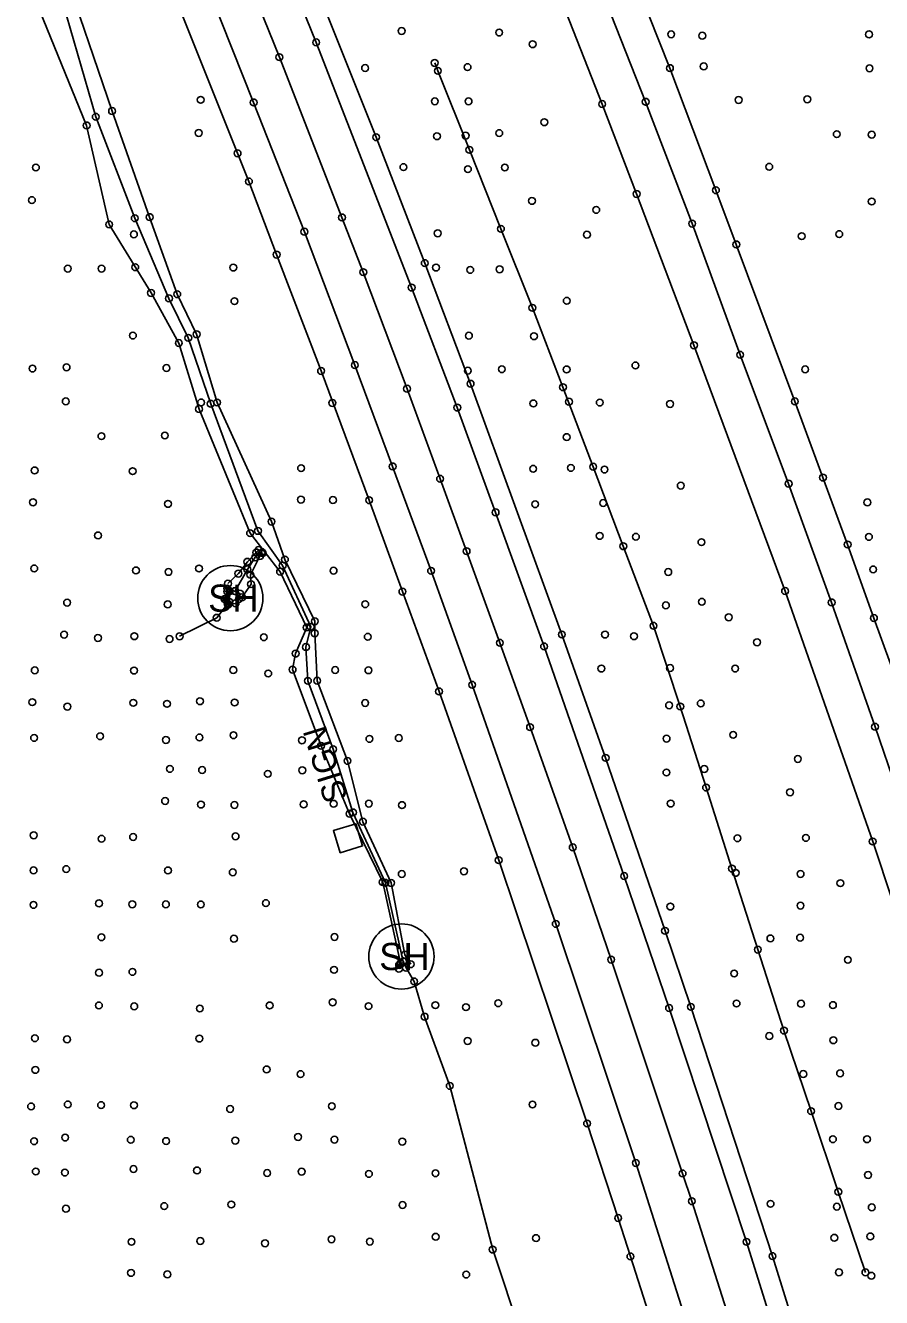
# Model space of a CAD drawing. Extents: x 20503438 to 20508873, y 7964251 to 7984667.
# Drawn here: x 20506193.5 to 20506445, y 7975096.9 to 7975470.8 of the extents above; entities that cross this region are included whole.
import ezdxf

# ---------------------------------------------------------------- set-up
doc = ezdxf.new("R2010")
doc.units = 0
for name, color, linetype in [('SurBreakLine', 7, 'Continuous'), ('SurDrainageArrowDown', 7, 'Continuous'), ('SurDrainageArrowUp', 7, 'Continuous'), ('SurEdgeRoadPaved', 7, 'Continuous'), ('SurEdgeShoulderPaved', 7, 'Continuous'), ('SurNaturalCells', 7, 'Continuous'), ('SurRoadPoints', 7, 'Continuous'), ('SurSurveyPoints', 7, 'Continuous')]:
    doc.layers.add(name, color=color, linetype=linetype)

msp = doc.modelspace()

# ---------------------------------------------------------------- linework, layer by layer
at = {"layer": 'SurBreakLine'}
for points in [[(20506254.12, 7975496.18), (20506268.1, 7975461.5), (20506286.48, 7975414.39), (20506292.75, 7975398.31), (20506305.6, 7975364.06), (20506315.32, 7975337.59), (20506323.1, 7975316.32), (20506332.87, 7975289.39), (20506341.75, 7975264.58), (20506354.3, 7975229.25), (20506365.58, 7975196.27), (20506386.55, 7975133.43), (20506389.28, 7975125.26), (20506400.17, 7975091.1)], [(20506204.02, 7975489.57), (20506218.94, 7975445.66), (20506229.98, 7975414.5), (20506238.08, 7975391.82), (20506243.78, 7975380.06), (20506249.79, 7975360.01), (20506265.78, 7975325), (20506269.72, 7975313.85), (20506278.51, 7975295.7), (20506278.47, 7975292.17), (20506279.19, 7975278.24), (20506288.11, 7975254.67), (20506292.64, 7975236.81), (20506300.9, 7975218.8), (20506304.96, 7975197.71), (20506306.69, 7975194.92)], [(20506193.49, 7975485.46), (20506211.46, 7975441.43), (20506218.08, 7975412.34), (20506230.39, 7975392.2), (20506238.56, 7975377.49), (20506244.49, 7975358.08), (20506259.5, 7975321.6), (20506268.3, 7975310.27), (20506276.12, 7975293.9), (20506272.86, 7975286.21), (20506271.97, 7975281.49), (20506280.33, 7975259.1), (20506288.72, 7975239.15), (20506298.46, 7975219.05), (20506303.7, 7975195.21), (20506303.27, 7975194.67)], [(20506349.14, 7975482.98), (20506362.94, 7975447.73), (20506373.06, 7975421.29), (20506389.9, 7975376.81), (20506416.68, 7975304.59), (20506442.42, 7975230.98), (20506465.81, 7975160.63), (20506487.25, 7975093.26), (20506498.75, 7975056.68), (20506509.78, 7975020.48), (20506520.41, 7974984.15), (20506530.78, 7974947.69), (20506540.38, 7974913.1), (20506559, 7974844.57), (20506576.27, 7974776.6), (20506593.8, 7974705.89)], [(20506261.97, 7975316.64), (20506261.31, 7975315.93), (20506258.68, 7975313.19), (20506256.04, 7975309.71), (20506252.98, 7975306.78)], [(20506256.18, 7975302.21), (20506257.1, 7975302.73), (20506259.76, 7975306.61), (20506259.58, 7975309.35), (20506262.39, 7975314.88), (20506263.18, 7975315.75)]]:
    msp.add_lwpolyline(points, dxfattribs=at)
for points in [[(20506252.82, 7975304.45), (20506252.04, 7975302.25), (20506253.13, 7975300.69), (20506255.22, 7975300.98), (20506256.18, 7975302.21), (20506256.51, 7975303.84), (20506254.95, 7975304.57), (20506252.76, 7975305.32)], [(20506252.5, 7975302.42), (20506253.42, 7975301.39), (20506253.53, 7975304.58)]]:
    msp.add_lwpolyline(points, close=True, dxfattribs=at)
at = {"layer": 'SurDrainageArrowDown'}
msp.add_lwpolyline([(20506440.28, 7975104.35), (20506432.3, 7975128.04), (20506424.32, 7975151.73), (20506416.34, 7975175.42), (20506408.66, 7975199.21), (20506401.07, 7975223.03), (20506393.47, 7975246.84), (20506385.88, 7975270.66), (20506378.02, 7975294.38), (20506369.15, 7975317.76), (20506360.29, 7975341.13), (20506351.42, 7975364.5), (20506342.43, 7975387.83), (20506333.17, 7975411.05), (20506323.91, 7975434.26), (20506314.65, 7975457.48), (20506313.72, 7975459.79)], dxfattribs=at)
at = {"layer": 'SurDrainageArrowUp'}
for points in [[(20506201.29, 7975488.71), (20506214.15, 7975443.99), (20506225.6, 7975414.16), (20506235.66, 7975390.61), (20506241.33, 7975379.02), (20506247.91, 7975359.64), (20506261.81, 7975322.26), (20506269.05, 7975312.08), (20506277.29, 7975294.07), (20506275.9, 7975288.13), (20506276.47, 7975278.21), (20506283.9, 7975258.08), (20506289.71, 7975239.53), (20506299.25, 7975218.85), (20506304.47, 7975195.73), (20506305.3, 7975193.87), (20506307.7, 7975189.86), (20506310.76, 7975179.49), (20506318.16, 7975159.16), (20506330.76, 7975111.05), (20506339.21, 7975085.68)], [(20506263.03, 7975316.04), (20506261.03, 7975314.52), (20506258.7, 7975310.97), (20506255.1, 7975304.62)], [(20506252.9, 7975300.86), (20506249.69, 7975296.74), (20506238.79, 7975291.29)]]:
    msp.add_lwpolyline(points, dxfattribs=at)
at = {"layer": 'SurEdgeRoadPaved'}
for points in [[(20506532.64, 7974648.96), (20506516.06, 7974719.27), (20506506.62, 7974757.3), (20506498.09, 7974790.71), (20506488.67, 7974827.17), (20506478.91, 7974863.97), (20506468.84, 7974900.69), (20506458.86, 7974936.07), (20506448.53, 7974971.96), (20506417.96, 7975072.9), (20506405.34, 7975113.32), (20506382.6, 7975182.03), (20506369.4, 7975220.83), (20506345.88, 7975288.32), (20506331.62, 7975327.71), (20506320.36, 7975358.51), (20506306.95, 7975393.79), (20506278.91, 7975465.84), (20506257.71, 7975518.12)], [(20506367.4, 7975497.02), (20506382.84, 7975458.29), (20506396.34, 7975422.39), (20506402.33, 7975406.46), (20506419.54, 7975360.34), (20506427.81, 7975337.94), (20506435.05, 7975318.28), (20506442.77, 7975296.67), (20506447.6, 7975283.16), (20506459.75, 7975248.31), (20506474.87, 7975203.27), (20506484.19, 7975175.26), (20506494.28, 7975143.45), (20506508.53, 7975099.05), (20506530.67, 7975027.95), (20506542.03, 7974988.95), (20506557.31, 7974934.61), (20506564.1, 7974910.06), (20506570.08, 7974888.15), (20506579.93, 7974851.7), (20506590.35, 7974810.45), (20506601.11, 7974767.59), (20506615.26, 7974710.46)], [(20506618.24, 7974651.55), (20506601.4, 7974722.56), (20506592.63, 7974758.41), (20506583.52, 7974795.39), (20506564.42, 7974869.18), (20506554.39, 7974905.89), (20506543.98, 7974943.66), (20506534.13, 7974978.72), (20506523.8, 7975014.27), (20506515.58, 7975041.4), (20506512.29, 7975052.25), (20506490.77, 7975121.09), (20506467.72, 7975192.09), (20506455.87, 7975227.47), (20506443.11, 7975264.71), (20506430.35, 7975301.25), (20506417.72, 7975336.15), (20506403.48, 7975374.04), (20506389.38, 7975412.58), (20506375.71, 7975448.39), (20506362.64, 7975481.5)], [(20506381.79, 7975075.91), (20506371.23, 7975109.03), (20506367.64, 7975120.33), (20506358.51, 7975148.1), (20506332.54, 7975225.5), (20506315, 7975275.08), (20506304.25, 7975304.42), (20506294.47, 7975331.29), (20506280.35, 7975369.28), (20506267.29, 7975403.46), (20506259.14, 7975424.98), (20506255.81, 7975433.25), (20506237.19, 7975479.91)], [(20506247.96, 7975479.81), (20506260.54, 7975448.2), (20506275.43, 7975410.2), (20506290.26, 7975371.02), (20506301.37, 7975341.22), (20506312.67, 7975310.54), (20506324.74, 7975277.04), (20506349.3, 7975206.77), (20506372.83, 7975136.5), (20506386.78, 7975092.48), (20506394.92, 7975066.92), (20506406.39, 7975029.37), (20506415.61, 7974999.14), (20506420.57, 7974982.55), (20506427.17, 7974960.41), (20506437.15, 7974925.73), (20506446.74, 7974891.45), (20506465.93, 7974820.14), (20506474.65, 7974785.33), (20506483.51, 7974751.12), (20506492.4, 7974715.32)]]:
    msp.add_lwpolyline(points, dxfattribs=at)
at = {"layer": 'SurEdgeShoulderPaved'}
msp.add_lwpolyline([(20506267.06, 7975511.74), (20506296.53, 7975437.96), (20506310.81, 7975400.98), (20506324.27, 7975365.52), (20506351.09, 7975291.82), (20506363.94, 7975255.58), (20506381.4, 7975204.73), (20506388.98, 7975182.4), (20506412.98, 7975109.14), (20506424.35, 7975072.59), (20506457.56, 7974962.26), (20506468.15, 7974925.5), (20506488.59, 7974852.02), (20506498.44, 7974814.69), (20506507.99, 7974777.45), (20506517.02, 7974741.08), (20506525.96, 7974704.19)], dxfattribs=at)
at = {"layer": 'SurNaturalCells'}
for centre in [(20506253.69, 7975302.51), (20506303.95, 7975197.19)]:
    msp.add_circle(centre, 9.59, dxfattribs=at)
at = {"layer": 'SurRoadPoints'}
msp.add_lwpolyline([(20506291.51, 7975232.95), (20506291.51, 7975232.95), (20506290.51, 7975236.22), (20506283.96, 7975234.21), (20506285.97, 7975227.66), (20506292.52, 7975229.67), (20506291.51, 7975232.95)], dxfattribs=at)
at = {"layer": 'SurSurveyPoints'}
for centre in [(20506304.01, 7975469.19), (20506332.67, 7975468.73), (20506383.2, 7975468.21), (20506441.33, 7975468.2), (20506278.91, 7975465.84), (20506342.5, 7975465.31), (20506392.35, 7975467.81), (20506268.1, 7975461.5), (20506293.29, 7975458.31), (20506313.72, 7975459.79), (20506314.65, 7975457.48), (20506323.38, 7975458.58), (20506382.84, 7975458.29), (20506392.76, 7975458.79), (20506441.48, 7975458.22), (20506218.94, 7975445.66), (20506244.97, 7975448.96), (20506260.54, 7975448.2), (20506313.76, 7975448.52), (20506323.67, 7975448.52), (20506362.94, 7975447.73), (20506375.71, 7975448.39), (20506403.02, 7975448.93), (20506423.19, 7975449.12), (20506214.15, 7975443.99), (20506345.92, 7975442.38), (20506211.46, 7975441.43), (20506244.39, 7975439.23), (20506314.39, 7975438.26), (20506322.82, 7975438.43), (20506332.69, 7975439.19), (20506431.85, 7975438.87), (20506442.12, 7975438.72), (20506296.53, 7975437.96), (20506255.81, 7975433.25), (20506323.91, 7975434.26), (20506196.55, 7975429.07), (20506304.54, 7975429.18), (20506323.48, 7975428.58), (20506334.33, 7975429.08), (20506412.01, 7975429.28), (20506259.14, 7975424.98), (20506195.39, 7975419.49), (20506373.06, 7975421.29), (20506396.34, 7975422.39), (20506342.3, 7975419.25), (20506361.19, 7975416.61), (20506442.13, 7975419.08), (20506218.08, 7975412.34), (20506225.6, 7975414.16), (20506229.98, 7975414.5), (20506286.48, 7975414.39), (20506389.38, 7975412.58), (20506225.35, 7975409.42), (20506275.43, 7975410.2), (20506314.62, 7975409.73), (20506333.17, 7975411.05), (20506358.46, 7975409.33), (20506421.55, 7975408.89), (20506432.58, 7975409.49), (20506402.33, 7975406.46), (20506267.29, 7975403.46), (20506310.81, 7975400.98), (20506205.93, 7975399.35), (20506215.85, 7975399.35), (20506225.74, 7975399.77), (20506254.56, 7975399.66), (20506292.75, 7975398.31), (20506314.13, 7975399.67), (20506324.16, 7975398.98), (20506332.81, 7975399.16), (20506306.95, 7975393.79), (20506230.39, 7975392.2), (20506235.66, 7975390.61), (20506238.08, 7975391.82), (20506254.89, 7975389.79), (20506352.54, 7975389.9), (20506342.43, 7975387.83), (20506225.05, 7975379.68), (20506241.33, 7975379.02), (20506243.78, 7975380.06), (20506323.77, 7975379.64), (20506342.9, 7975379.49), (20506238.56, 7975377.49), (20506389.9, 7975376.81), (20506290.26, 7975371.02), (20506372.7, 7975370.9), (20506403.48, 7975374.04), (20506195.57, 7975369.98), (20506205.57, 7975370.36), (20506234.91, 7975370.13), (20506280.35, 7975369.28), (20506323.47, 7975369.36), (20506333.46, 7975369.78), (20506352.49, 7975369.72), (20506422.57, 7975369.75), (20506305.6, 7975364.06), (20506324.27, 7975365.52), (20506351.42, 7975364.5), (20506205.34, 7975360.34), (20506245.09, 7975360.03), (20506247.91, 7975359.64), (20506249.79, 7975360.01), (20506283.66, 7975359.86), (20506342.72, 7975359.73), (20506353.17, 7975360.24), (20506362.22, 7975359.98), (20506382.87, 7975359.58), (20506419.54, 7975360.34), (20506244.49, 7975358.08), (20506320.36, 7975358.51), (20506215.82, 7975350.11), (20506234.45, 7975350.3), (20506352.52, 7975349.84), (20506301.37, 7975341.22), (20506360.29, 7975341.13), (20506196.19, 7975340.04), (20506224.99, 7975339.82), (20506274.48, 7975340.7), (20506315.32, 7975337.59), (20506342.66, 7975340.52), (20506353.75, 7975340.78), (20506363.62, 7975340.3), (20506427.81, 7975337.94), (20506386.02, 7975335.57), (20506417.72, 7975336.15), (20506195.71, 7975330.67), (20506235.37, 7975330.21), (20506274.44, 7975331.46), (20506283.84, 7975331.34), (20506294.47, 7975331.29), (20506343.25, 7975330.1), (20506363.22, 7975330.46), (20506440.85, 7975330.65), (20506331.62, 7975327.71), (20506261.81, 7975322.26), (20506265.78, 7975325), (20506214.81, 7975320.94), (20506259.5, 7975321.6), (20506362.2, 7975320.8), (20506372.84, 7975320.55), (20506392.1, 7975318.95), (20506441.3, 7975320.51), (20506261.31, 7975315.93), (20506261.97, 7975316.64), (20506262.39, 7975314.88), (20506263.03, 7975316.04), (20506263.18, 7975315.75), (20506323.1, 7975316.32), (20506369.15, 7975317.76), (20506435.05, 7975318.28), (20506196.06, 7975311.23), (20506244.48, 7975311.22), (20506258.68, 7975313.19), (20506258.7, 7975310.97), (20506261.03, 7975314.52), (20506269.05, 7975312.08), (20506269.72, 7975313.85), (20506442.55, 7975310.95), (20506225.95, 7975310.65), (20506235.52, 7975310.21), (20506256.04, 7975309.71), (20506259.58, 7975309.35), (20506268.3, 7975310.27), (20506284.01, 7975310.58), (20506312.67, 7975310.54), (20506382.35, 7975310.19), (20506252.76, 7975305.32), (20506252.82, 7975304.45), (20506252.98, 7975306.78), (20506253.53, 7975304.58), (20506254.95, 7975304.57), (20506255.1, 7975304.62), (20506256.51, 7975303.84), (20506259.76, 7975306.61), (20506304.25, 7975304.42), (20506416.68, 7975304.59), (20506205.73, 7975301.19), (20506235.28, 7975300.68), (20506252.04, 7975302.25), (20506252.5, 7975302.42), (20506252.9, 7975300.86), (20506253.13, 7975300.69), (20506253.42, 7975301.39), (20506255.22, 7975300.98), (20506256.18, 7975302.21), (20506257.1, 7975302.73), (20506293.31, 7975300.72), (20506381.65, 7975300.38), (20506392.22, 7975301.44), (20506430.35, 7975301.25), (20506249.69, 7975296.74), (20506400.1, 7975296.87), (20506442.77, 7975296.67), (20506276.12, 7975293.9), (20506277.29, 7975294.07), (20506278.51, 7975295.7), (20506378.02, 7975294.38), (20506204.84, 7975291.78), (20506214.8, 7975290.8), (20506225.48, 7975291.32), (20506235.83, 7975290.5), (20506238.79, 7975291.29), (20506263.53, 7975291.01), (20506278.47, 7975292.17), (20506294.06, 7975291.15), (20506332.87, 7975289.39), (20506351.09, 7975291.82), (20506363.77, 7975291.8), (20506372.28, 7975291.32), (20506408.43, 7975289.53), (20506272.86, 7975286.21), (20506275.9, 7975288.13), (20506345.88, 7975288.32), (20506196.23, 7975281.27), (20506225.4, 7975281.23), (20506254.55, 7975281.38), (20506271.97, 7975281.49), (20506284.49, 7975281.37), (20506294.27, 7975281.31), (20506362.7, 7975281.81), (20506382.88, 7975281.96), (20506402, 7975281.81), (20506264.82, 7975280.36), (20506276.47, 7975278.21), (20506279.19, 7975278.24), (20506315, 7975275.08), (20506324.74, 7975277.04), (20506195.5, 7975271.93), (20506205.8, 7975270.63), (20506225.17, 7975271.73), (20506235.08, 7975271.45), (20506244.76, 7975272.2), (20506254.94, 7975271.83), (20506293.3, 7975271.69), (20506382.59, 7975271.02), (20506385.88, 7975270.66), (20506391.9, 7975271.56), (20506341.75, 7975264.58), (20506401.42, 7975262.33), (20506443.11, 7975264.71), (20506196.03, 7975261.43), (20506215.43, 7975261.92), (20506234.78, 7975260.83), (20506244.6, 7975261.56), (20506254.61, 7975262.22), (20506274.74, 7975260.73), (20506280.33, 7975259.1), (20506294.56, 7975261.14), (20506303.18, 7975261.39), (20506381.85, 7975261.21), (20506283.9, 7975258.08), (20506363.94, 7975255.58), (20506420.41, 7975255.24), (20506235.93, 7975252.32), (20506245.39, 7975251.98), (20506274.82, 7975251.91), (20506288.11, 7975254.67), (20506381.81, 7975251.26), (20506392.94, 7975252.29), (20506264.69, 7975250.87), (20506393.47, 7975246.84), (20506418.13, 7975245.44), (20506234.53, 7975242.9), (20506245.06, 7975241.84), (20506254.89, 7975241.72), (20506275.23, 7975241.89), (20506284.04, 7975242.08), (20506294.38, 7975242.12), (20506304.12, 7975241.68), (20506383.06, 7975242.14), (20506288.72, 7975239.15), (20506289.71, 7975239.53), (20506292.64, 7975236.81), (20506195.92, 7975232.81), (20506255.23, 7975232.51), (20506215.85, 7975231.79), (20506225.11, 7975232.32), (20506354.3, 7975229.25), (20506402.68, 7975231.94), (20506422.79, 7975232.05), (20506442.42, 7975230.98), (20506332.54, 7975225.5), (20506195.87, 7975222.49), (20506205.47, 7975222.88), (20506235.36, 7975222.47), (20506254.4, 7975221.94), (20506304.05, 7975221.42), (20506322.33, 7975222.22), (20506401.07, 7975223.03), (20506402.15, 7975221.76), (20506421.22, 7975221.45), (20506298.46, 7975219.05), (20506299.25, 7975218.85), (20506300.9, 7975218.8), (20506369.4, 7975220.83), (20506432.91, 7975218.74), (20506195.86, 7975212.35), (20506215.1, 7975212.8), (20506224.88, 7975212.52), (20506234.75, 7975212.5), (20506245.01, 7975212.48), (20506264.14, 7975212.87), (20506382.96, 7975211.86), (20506421.2, 7975212.14), (20506349.3, 7975206.77), (20506215.82, 7975202.84), (20506284.29, 7975202.93), (20506381.4, 7975204.73), (20506412.36, 7975202.5), (20506421.09, 7975202.7), (20506254.75, 7975202.41), (20506408.66, 7975199.21), (20506303.7, 7975195.21), (20506304.47, 7975195.73), (20506304.96, 7975197.71), (20506365.58, 7975196.27), (20506435.11, 7975196.2), (20506215.11, 7975192.42), (20506224.93, 7975192.66), (20506284.15, 7975193.26), (20506303.23, 7975193.59), (20506303.27, 7975194.67), (20506305.3, 7975193.87), (20506306.69, 7975194.92), (20506401.72, 7975192.19), (20506307.7, 7975189.86), (20506215.06, 7975182.8), (20506225.45, 7975182.53), (20506244.72, 7975181.91), (20506265.24, 7975182.8), (20506283.75, 7975183.72), (20506294.3, 7975182.59), (20506313.92, 7975182.89), (20506322.91, 7975182.3), (20506332.39, 7975183.45), (20506382.6, 7975182.03), (20506388.98, 7975182.4), (20506402.41, 7975183.38), (20506421.36, 7975183.31), (20506430.73, 7975182.9), (20506310.76, 7975179.49), (20506196.27, 7975173.16), (20506205.7, 7975172.84), (20506244.59, 7975173.07), (20506412.04, 7975173.81), (20506416.34, 7975175.42), (20506323.41, 7975172.37), (20506343.3, 7975171.84), (20506430.86, 7975172.57), (20506196.4, 7975163.85), (20506264.35, 7975164), (20506274.32, 7975162.62), (20506422.03, 7975162.64), (20506432.83, 7975162.83), (20506318.16, 7975159.16), (20506195.15, 7975153.12), (20506205.93, 7975153.71), (20506215.71, 7975153.51), (20506225.37, 7975153.47), (20506253.61, 7975152.37), (20506283.51, 7975153.18), (20506342.47, 7975153.69), (20506424.32, 7975151.73), (20506432.34, 7975153.24), (20506358.51, 7975148.1), (20506196.03, 7975142.9), (20506205.15, 7975143.98), (20506224.43, 7975143.32), (20506234.81, 7975142.94), (20506255.15, 7975143.07), (20506273.57, 7975144.15), (20506284.27, 7975143.36), (20506304.21, 7975142.78), (20506430.72, 7975143.49), (20506440.75, 7975143.49), (20506372.83, 7975136.5), (20506196.53, 7975134), (20506205.08, 7975133.69), (20506225.24, 7975134.72), (20506243.9, 7975134.3), (20506264.5, 7975133.55), (20506274.63, 7975133.95), (20506294.4, 7975133.29), (20506313.96, 7975133.48), (20506386.55, 7975133.43), (20506441.04, 7975132.97), (20506432.3, 7975128.04), (20506253.97, 7975124.3), (20506304.29, 7975124.15), (20506389.28, 7975125.26), (20506412.41, 7975124.5), (20506205.39, 7975123.07), (20506234.27, 7975123.82), (20506367.64, 7975120.33), (20506431.87, 7975123.66), (20506442.15, 7975123.45), (20506224.64, 7975113.33), (20506244.86, 7975113.57), (20506263.88, 7975112.9), (20506283.4, 7975114.08), (20506294.67, 7975113.38), (20506314.03, 7975114.82), (20506343.5, 7975114.43), (20506405.34, 7975113.32), (20506431.13, 7975114.52), (20506441.71, 7975114.91), (20506330.76, 7975111.05), (20506412.98, 7975109.14), (20506371.23, 7975109.03), (20506224.52, 7975104.19), (20506235.19, 7975103.77), (20506323, 7975103.71), (20506432.51, 7975104.36), (20506440.28, 7975104.35), (20506442.03, 7975103.36)]:
    msp.add_circle(centre, 1, dxfattribs=at)

# ---------------------------------------------------------------- texts
at = {"layer": 'SurNaturalCells'}
for p in [(20506247.17, 7975298.51), (20506297.43, 7975193.19)]:
    msp.add_text('SH', height=7.995, rotation=360, dxfattribs=at).set_placement(p)
at = {"layer": 'SurRoadPoints'}
msp.add_text('SIGN', height=6.995, rotation=107.094, dxfattribs=at).set_placement((20506288.29, 7975243.68))

doc.saveas('drawing.dxf')
